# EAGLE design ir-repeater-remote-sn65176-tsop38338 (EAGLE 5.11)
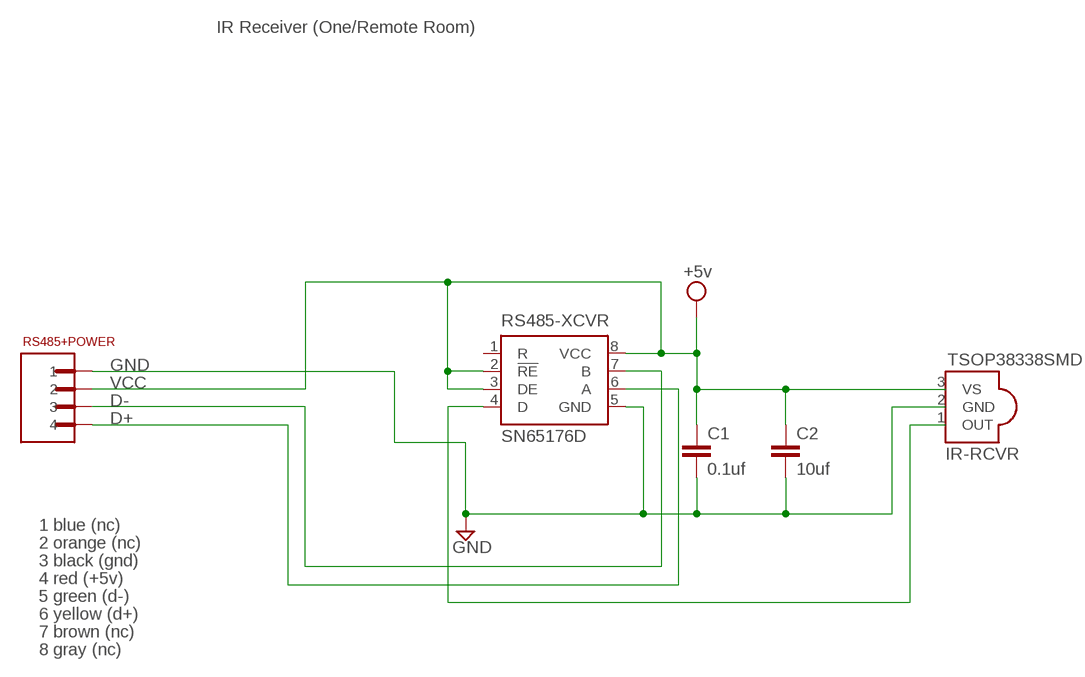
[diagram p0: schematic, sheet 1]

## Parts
C1  0.1uf  C-EUC0805  [C0805]
C2  10uf  C-EUC1206  [C1206]
IR-RCVR  TSOP38338SMD  [3SIL-SMD]
RS485+POWER  HEADER4-SMD  [4SIL-SMD]
RS485-XCVR  SN65176D  [SO-08]

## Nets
D+: RS485+POWER.4 RS485-XCVR.6(A)
D-: RS485+POWER.3 RS485-XCVR.7(B)
GND: C1.2 C2.2 IR-RCVR.2(GND) RS485+POWER.1 RS485-XCVR.5(GND)
N$6: IR-RCVR.1(OUT) RS485-XCVR.4(D)
VCC: C1.1 C2.1 IR-RCVR.3(VS) RS485+POWER.2 RS485-XCVR.2(!RE) RS485-XCVR.3(DE) RS485-XCVR.8(VCC) ; supply symbol labelled +5v
Unconnected: RS485-XCVR.1(R)

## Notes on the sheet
- IR Receiver (One/Remote Room)
- 1 blue (nc)
- 2 orange (nc)
- 3 black (gnd)
- 4 red (+5v)
- 5 green (d-)
- 6 yellow (d+)
- 7 brown (nc)
- 8 gray (nc)

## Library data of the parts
C1 C2 = rcl:C-EU: CAPACITOR, European symbol
IR-RCVR = trl:TSOP38338
RS485+POWER = trl:HEADER4-SMD
RS485-XCVR = texas:SN65176: DIFFERENTIAL BUS TRANSCEIVER Source: http://focus.ti.com .. sn65176b.pdf; MF: TEXAS INSTRUMENTS; MPN: SN65176BD; OC_FARNELL: 9589970; OC_NEWARK: 08F5891

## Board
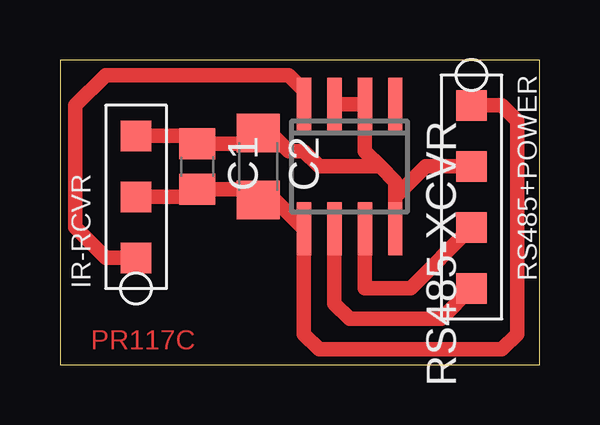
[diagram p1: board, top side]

Size 19.99 x 12.69 mm. Coordinates in mm from the lower left corner, seen from the top.
Outline: 0,0 19.99,0 19.99,12.69 0,12.69 0,0
Copper layers (1*16): Top 0.035mm / dielectric 1.5mm / Bottom 0.035mm
Design rules "default": minimum track width 10mil, minimum drill 24mil, track to track 8mil, track to pad 8mil, pad to pad 8mil, via to via 8mil, smd to smd 8mil, copper to edge 40mil, drill to drill 8mil, minimum pad ring 10mil, minimum via ring 8mil, stop-mask expansion 4mil, vias tented up to drill 0mil, thermal gap 10mil

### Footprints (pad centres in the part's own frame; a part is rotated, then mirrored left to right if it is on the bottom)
C0805 = smd 1.3 x 1.5: 1 -0.95,0; 2 0.95,0
C1206 = smd 1.6 x 1.8: 1 -1.4,0; 2 1.4,0
3SIL-SMD = smd 1.27 x 1.27: 1 -2.54,0; 2 0,0; 3 2.54,0
4SIL-SMD = smd 1.27 x 1.27: 1 -5.08,0; 2 -2.54,0; 3 0,0; 4 2.54,0
SO-08 = smd 0.6 x 2.2: 1 -1.905,-2.6; 2 -0.635,-2.6; 3 0.635,-2.6; 4 1.905,-2.6; 5 1.905,2.6; 6 0.635,2.6; 7 -0.635,2.6; 8 -1.905,2.6

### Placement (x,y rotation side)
C1  5.71,8.26 270 top
C2  8.26,8.26 270 top
IR-RCVR  3.17,6.99 90 top
RS485+POWER  17.14,5.71 270 top
RS485-XCVR  12.06,8.26 180 top

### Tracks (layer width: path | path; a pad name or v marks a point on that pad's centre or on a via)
D+
  Top 0.61: RS485+POWER.4 15.88,1.91 12.06,1.91 11.43,2.54 RS485-XCVR.6
D-
  Top 0.61: RS485-XCVR.7 12.7,3.17 14.61,3.17 RS485+POWER.3
GND
  Top 0.61: IR-RCVR.2 5.39,6.99 C1.2 7.8,7.3 C2.2 8.96,6.86 RS485-XCVR.5 10.16,1.27 10.79,0.64 18.41,0.64 19.05,1.27 19.05,10.16 18.41,10.79 RS485+POWER.1
N$6
  Top 0.61: IR-RCVR.1 1.91,4.45 0.64,5.71 0.64,10.79 1.91,12.06 9.53,12.06 10.16,11.43 RS485-XCVR.4
VCC
  Top 0.61: IR-RCVR.3 5.39,9.53 C1.1 7.8,9.21 C2.1 8.76,9.65 9.53,8.89 10.16,8.89 10.79,8.26 13.34,8.26 | RS485-XCVR.3 RS485-XCVR.2 12.7,8.89 13.34,8.26 | 13.34,8.26 13.97,7.62 13.97,6.99 | 13.97,6.99 RS485-XCVR.8 | RS485+POWER.2 15.24,8.26 13.97,6.99

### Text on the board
Top: PR117C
